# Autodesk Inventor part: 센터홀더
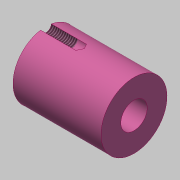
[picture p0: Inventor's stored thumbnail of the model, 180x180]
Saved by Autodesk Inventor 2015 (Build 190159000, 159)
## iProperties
Created: 2019-10
Part Number: 센터홀더
Material: 강철, 연강
Document SubType Name: Modeling
Designer: mduedu
Density: 1 g/cm^3
Appearance: 분홍색
Author: mduedu
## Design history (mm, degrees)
sketch "스케치1"
  geometry: L1 (0, 0)-(20, 0); L2 (12, -3)-(20, -3); L3 (20, -3)-(20, -7.5); L4 (20, -7.5)-(0, -7.5); L5 (0, -7.5)-(0, -4.127); L6 (0, -4.127)-(12, -3.751); L7 (12, -3.751)-(12, -3)
  constraints: 14 end point, 2 horizontal, 2 parallel, 2 perpendicular, 2 vertical alignment
  dimensions: "d0" = 20 distance of L1.start L1.end; "d1" = 6 diameter of L2 L1; "d2" = 12 distance between parallel lines of L5 L7; "d3" = 7.502 diameter of L6.end L1; "d4" = 8.254 diameter of L5.end L1; "d5" = 15 diameter of L4 L1
revolve "회전1" sketch "스케치1" stored, may be unused: angle "d6" = 90 deg
sketch "스케치2"
  geometry: 3 further points
  constraints: 2 vertical alignment, 1 other
hole "구멍1" sketch "스케치2" at (0, 7.5) diameter "d7" = 2.459; stored, may be unused: countersink angle "d11" = 90 deg, drill point angle "d13" = 118 deg; dims "d8" = 6, "d9" = 4, "d10" = 2, "d12" = 8
node "솔리드1"
